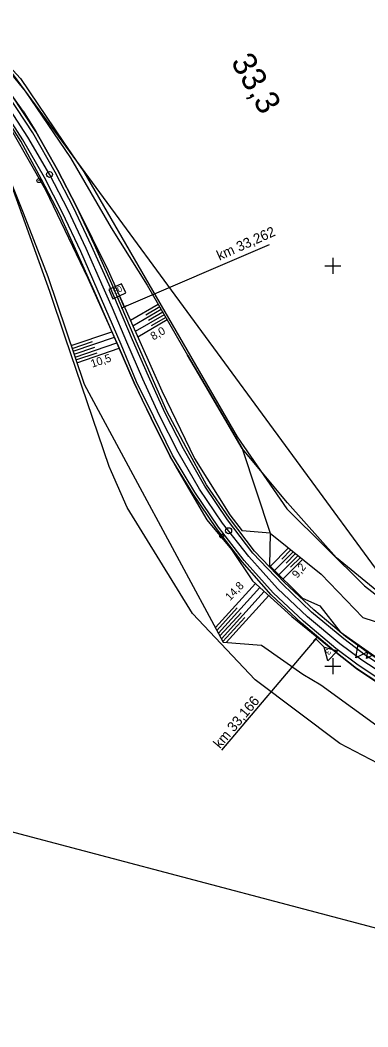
# Model space of a CAD drawing. Extents: x -805011 to -803920, y -1150790 to -1150234.
# Drawn here: x -804178.2 to -804091.2, y -1150790.1 to -1150538.7 of the extents above; entities that cross this region are included whole.
import ezdxf

# ---------------------------------------------------------------- set-up
doc = ezdxf.new("R2010")
doc.units = 0
for name, color, linetype in [('0381KM032-037P - Vrstva 1', 7, 'Continuous'), ('0381KM032-037P - Vrstva 17', 7, 'Continuous'), ('0381KM032-037P - Vrstva 4', 7, 'Continuous'), ('0381KM032-037P - Vrstva 48', 7, 'Continuous'), ('0381KM032-037P - Vrstva 49', 7, 'Continuous'), ('0381KM032-037P - Vrstva 5', 7, 'Continuous'), ('0381KM032-037P - Vrstva 50', 7, 'Continuous'), ('0381KM032-037P - Vrstva 7', 7, 'Continuous'), ('formát', 7, 'Continuous'), ('hran DP - hran DP', 7, 'Continuous'), ('krizky_1000 - Vrstva 1', 7, 'Continuous'), ('vyt_sit - polygon', 7, 'Continuous')]:
    doc.layers.add(name, color=color, linetype=linetype)

msp = doc.modelspace()

# ---------------------------------------------------------------- linework, layer by layer
at = {"layer": '0381KM032-037P - Vrstva 1'}
for points in [[(-804170.82, -1150577.3), (-804176.26, -1150567.85), (-804182.37, -1150558.45), (-804188.8, -1150549.63), (-804195.8, -1150541.09), (-804203.2, -1150532.98), (-804210.73, -1150525.57), (-804219.76, -1150517.68), (-804222.98, -1150515.09)], [(-804121.06, -1150672.62), (-804127.59, -1150664.31), (-804133.36, -1150655.8), (-804138.71, -1150646.59), (-804143.42, -1150637.27), (-804147.52, -1150628.35), (-804151.54, -1150619.12), (-804155.16, -1150610.64), (-804157.42, -1150605.4), (-804161.72, -1150595.74), (-804166.25, -1150586.16), (-804170.82, -1150577.3)], [(-803978.41, -1150722.71), (-803983.51, -1150723.68), (-803993.92, -1150724.91), (-804004.46, -1150725.42), (-804014.95, -1150725.21), (-804025.47, -1150724.25), (-804035.41, -1150722.67), (-804044.08, -1150720.74), (-804054.77, -1150717.61), (-804064.47, -1150714.03), (-804074.16, -1150709.61), (-804083.95, -1150704.25), (-804092.73, -1150698.52), (-804098.22, -1150694.46), (-804106.33, -1150687.73), (-804113.82, -1150680.6), (-804121.06, -1150672.62)]]:
    msp.add_lwpolyline(points, dxfattribs=at)
at = {"layer": '0381KM032-037P - Vrstva 17'}
for points in [[(-804099.12, -1150672.95), (-804111.38, -1150659.24), (-804122.71, -1150645.64), (-804131.91, -1150629.82), (-804136.37, -1150622.31)], [(-804059.54, -1150698.86), (-804062.04, -1150700.07), (-804077.59, -1150690.55), (-804099.12, -1150672.95)]]:
    msp.add_lwpolyline(points, dxfattribs=at)
at = {"layer": '0381KM032-037P - Vrstva 4'}
for points in [[(-804155.31, -1150604.52), (-804159.65, -1150594.76), (-804164.13, -1150585.17), (-804168.86, -1150576.08), (-804174.28, -1150566.45), (-804180.44, -1150557.11), (-804187.11, -1150547.91)], [(-804159.67, -1150606.25), (-804163.99, -1150596.78), (-804168.29, -1150587.2), (-804172.88, -1150578.5), (-804178.08, -1150568.91), (-804181.43, -1150563.5), (-804184.18, -1150559.55), (-804190.46, -1150550.87)], [(-804158.94, -1150605.89), (-804163.07, -1150596.41), (-804167.66, -1150586.77), (-804172.11, -1150577.99), (-804177.55, -1150568.56), (-804183.56, -1150559.32), (-804190.06, -1150550.44)], [(-804155.96, -1150604.81), (-804160.35, -1150595.07), (-804164.87, -1150585.5), (-804169.43, -1150576.62), (-804175.01, -1150566.82), (-804181.12, -1150557.55), (-804187.68, -1150548.56)], [(-804135, -1150656.89), (-804140.73, -1150647.62), (-804145.48, -1150638.07), (-804149.71, -1150629.27), (-804153.71, -1150619.99), (-804159.67, -1150606.25)], [(-804134.56, -1150656.61), (-804140.15, -1150647.32), (-804144.81, -1150637.78), (-804149.09, -1150628.99), (-804152.99, -1150619.67), (-804158.94, -1150605.89)], [(-804132.06, -1150655.06), (-804137.36, -1150645.71), (-804142.06, -1150636.68), (-804146.12, -1150627.62), (-804150.08, -1150618.55), (-804155.96, -1150604.81)], [(-804131.6, -1150654.76), (-804136.67, -1150645.43), (-804141.53, -1150636.36), (-804145.41, -1150627.43), (-804149.44, -1150618.25), (-804155.31, -1150604.52)], [(-804073.38, -1150708.29), (-804083.27, -1150702.88), (-804091.89, -1150697.28), (-804097.27, -1150693.2), (-804105.34, -1150686.53), (-804112.64, -1150679.57), (-804120.03, -1150671.79), (-804126.35, -1150663.48), (-804132.06, -1150655.06)], [(-804073.1, -1150707.59), (-804077.68, -1150705.14), (-804082.78, -1150702.25), (-804091.44, -1150696.56), (-804096.83, -1150692.65), (-804104.73, -1150685.98), (-804112.1, -1150679.17), (-804119.6, -1150671.34), (-804125.86, -1150663.1), (-804131.6, -1150654.76)], [(-804075.18, -1150711.95), (-804085.34, -1150706.36), (-804094.07, -1150700.58), (-804099.68, -1150696.17), (-804107.82, -1150689.29), (-804115.4, -1150682.25), (-804122.72, -1150674.01), (-804129.15, -1150665.64), (-804135, -1150656.89)], [(-804074.79, -1150711.15), (-804084.84, -1150705.62), (-804093.69, -1150699.81), (-804099.23, -1150695.65), (-804107.33, -1150688.8), (-804114.94, -1150681.73), (-804122.23, -1150673.64), (-804128.61, -1150665.3), (-804134.56, -1150656.61)]]:
    msp.add_lwpolyline(points, dxfattribs=at)
at = {"layer": '0381KM032-037P - Vrstva 48'}
for p, q in [((-804143.67, -1150609.66), (-804150.65, -1150613.69)), ((-804142.92, -1150610.96), (-804150.03, -1150615.07)), ((-804143.3, -1150610.31), (-804146.82, -1150612.35)), ((-804142.17, -1150612.26), (-804149.42, -1150616.44)), ((-804141.42, -1150613.56), (-804148.81, -1150617.82)), ((-804142.55, -1150611.61), (-804146.14, -1150613.68)), ((-804141.8, -1150612.91), (-804145.46, -1150615.02)), ((-804165.46, -1150619.97), (-804155.27, -1150616.52)), ((-804164.98, -1150621.39), (-804154.65, -1150617.89)), ((-804165.22, -1150620.68), (-804160.09, -1150618.94)), ((-804164.74, -1150622.1), (-804159.54, -1150620.34)), ((-804164.5, -1150622.81), (-804154.04, -1150619.27)), ((-804164.02, -1150624.23), (-804153.43, -1150620.64)), ((-804164.26, -1150623.52), (-804158.99, -1150621.74)), ((-804111.08, -1150670.5), (-804115.64, -1150675.08)), ((-804109.9, -1150671.45), (-804114.57, -1150676.14)), ((-804110.49, -1150670.98), (-804112.8, -1150673.29)), ((-804108.72, -1150672.39), (-804113.51, -1150677.2)), ((-804107.54, -1150673.33), (-804112.45, -1150678.26)), ((-804109.31, -1150671.92), (-804111.68, -1150674.29)), ((-804108.13, -1150672.86), (-804110.56, -1150675.3)), ((-804129.38, -1150690.39), (-804119.38, -1150679.38)), ((-804128.63, -1150691.79), (-804118.27, -1150680.39)), ((-804127.87, -1150693.19), (-804117.16, -1150681.39)), ((-804126.68, -1150694.11), (-804116.05, -1150682.4)), ((-804129.01, -1150691.09), (-804123.91, -1150685.49)), ((-804128.25, -1150692.49), (-804122.98, -1150686.69)), ((-804127.5, -1150693.89), (-804122.05, -1150687.9))]:
    msp.add_line(p, q, dxfattribs=at)
at = {"layer": '0381KM032-037P - Vrstva 49'}
for q in [(-804122.66, -1150666.25), (-804115.86, -1150674.86)]:
    msp.add_line((-804115.71, -1150666.79), q, dxfattribs=at)
for points in [[(-804216.26, -1150515.03), (-804196.49, -1150533.54), (-804188.66, -1150542.31), (-804183.72, -1150548.22), (-804177, -1150556.4), (-804165.66, -1150573.06), (-804155.49, -1150590.5), (-804146.45, -1150604.86), (-804136.37, -1150622.31), (-804131.91, -1150629.82), (-804122.71, -1150645.64), (-804115.71, -1150666.79), (-804102.89, -1150677.06), (-804092.51, -1150687.92), (-804076.71, -1150692.97), (-804062.72, -1150701.97), (-804052.08, -1150706.52)], [(-804177.46, -1150561.39), (-804180.44, -1150557.11), (-804187.34, -1150547.5), (-804194.06, -1150539.52)], [(-804190.46, -1150550.87), (-804184.18, -1150559.55), (-804171.89, -1150581.01)], [(-804191.88, -1150555.68), (-804187.09, -1150562.15), (-804183.47, -1150572.06), (-804177.47, -1150586.83), (-804171.32, -1150602.68), (-804162.19, -1150629.63), (-804127.41, -1150694.05), (-804117.85, -1150694.76), (-804107.49, -1150702.04), (-804103.03, -1150704.73), (-804070.42, -1150728.33), (-804053.81, -1150732.63), (-804001.62, -1150732.39)], [(-804177.46, -1150561.39), (-804174.28, -1150566.45), (-804168.86, -1150576.08), (-804164.13, -1150585.17), (-804156.2, -1150601.21), (-804142.82, -1150631.28), (-804134.64, -1150648.13), (-804125.75, -1150662.22), (-804122.66, -1150666.25)], [(-804171.89, -1150581.01), (-804161.29, -1150603.14), (-804153.71, -1150619.99), (-804149.71, -1150629.27), (-804147.81, -1150633.31), (-804145.48, -1150638.07), (-804140.73, -1150647.62), (-804139.02, -1150650.67), (-804131.55, -1150663.46), (-804125.32, -1150670.91), (-804120.07, -1150678.75), (-804110.3, -1150687.62), (-804101.36, -1150694.88), (-804099.68, -1150696.17), (-804094.07, -1150700.58), (-804090.5, -1150703.01), (-804085.34, -1150706.36), (-804081.43, -1150711.18)], [(-804115.86, -1150674.86), (-804107.6, -1150683.08), (-804103.3, -1150684.96), (-804098.16, -1150691.46), (-804087.29, -1150699.16)]]:
    msp.add_lwpolyline(points, dxfattribs=at)
at = {"layer": '0381KM032-037P - Vrstva 5'}
for p, q in [((-804152.17, -1150610.26), (-804115.82, -1150594.67)), ((-804152.87, -1150610.57), (-804151.5, -1150609.96)), ((-804104.29, -1150693.19), (-804127.82, -1150721.03)), ((-804103.76, -1150692.66), (-804104.82, -1150693.72))]:
    msp.add_line(p, q, dxfattribs=at)
for points in [[(-804152.18, -1150610.26), (-804153.41, -1150607.52), (-804151.81, -1150606.81), (-804152.83, -1150604.53), (-804156.03, -1150605.96), (-804155.01, -1150608.24), (-804153.41, -1150607.52)], [(-804104.29, -1150693.19), (-804102.17, -1150695.31), (-804098.81, -1150696.19), (-804101.28, -1150698.67), (-804102.17, -1150695.31)]]:
    msp.add_lwpolyline(points, dxfattribs=at)
at = {"layer": '0381KM032-037P - Vrstva 50'}
msp.add_lwpolyline([(-804090.07, -1150697.33), (-804091.56, -1150698.09), (-804091.28, -1150696.44), (-804094.26, -1150697.96), (-804093.69, -1150694.66)], dxfattribs=at)
at = {"layer": '0381KM032-037P - Vrstva 7'}
for p, q in [((-804173.51, -1150578.79), (-804173.56, -1150578.7)), ((-804127.76, -1150667.59), (-804127.82, -1150667.51))]:
    msp.add_line(p, q, dxfattribs=at)
for centre, radius in [((-804173.53, -1150578.75), 0.5), ((-804170.87, -1150577.21), 0.75), ((-804126.09, -1150666.21), 0.75), ((-804127.79, -1150667.55), 0.5)]:
    msp.add_circle(centre, radius, dxfattribs=at)
at = {"layer": 'formát'}
msp.add_line((-803996.25, -1150790.14), (-804199.27, -1150736.42), dxfattribs=at)
at = {"layer": 'hran DP - hran DP'}
for p, q in [((-804196.65, -1150533.37), (-804178.11, -1150553.27)), ((-804178.11, -1150553.27), (-804167.37, -1150569.11)), ((-804167.37, -1150569.11), (-804162.29, -1150576.56)), ((-804170.78, -1150606.46), (-804182.55, -1150573.8)), ((-804162.29, -1150576.56), (-804123.96, -1150642.72)), ((-804166.92, -1150617.84), (-804170.78, -1150606.46)), ((-804155.97, -1150650.2), (-804166.92, -1150617.84)), ((-804123.96, -1150642.72), (-804111.51, -1150660.72)), ((-804155.38, -1150651.53), (-804155.97, -1150650.2)), ((-804151.42, -1150660.42), (-804155.38, -1150651.53)), ((-804135.09, -1150686.84), (-804151.42, -1150660.42)), ((-804111.51, -1150660.72), (-804092.1, -1150680)), ((-804092.1, -1150680), (-804079.43, -1150689.81)), ((-804119.46, -1150703.45), (-804135.09, -1150686.84)), ((-804098.25, -1150719.35), (-804119.46, -1150703.45)), ((-804086.77, -1150725.31), (-804098.25, -1150719.35))]:
    msp.add_line(p, q, dxfattribs=at)
at = {"layer": 'krizky_1000 - Vrstva 1'}
for points in [[(-804100, -1150598), (-804100, -1150602)], [(-804102, -1150600), (-804098, -1150600)], [(-804100, -1150698), (-804100, -1150702)], [(-804102, -1150700), (-804098, -1150700)]]:
    msp.add_lwpolyline(points, dxfattribs=at)
at = {"layer": 'vyt_sit - polygon'}
msp.add_line((-804184.81, -1150545.81), (-804054.72, -1150722.82), dxfattribs=at)

# ---------------------------------------------------------------- texts
at = {"layer": '0381KM032-037P - Vrstva 48'}
for s, rotation, p in [('8,0', 29.9889, (-804144.91, -1150618.69)), ('10,5', 18.3536, (-804160.19, -1150625.49)), ('9,2', 51.2857, (-804108.89, -1150678.22)), ('14,8', 45.8956, (-804125.73, -1150683.84))]:
    msp.add_text(s, height=2, rotation=rotation, dxfattribs=at).set_placement(p)
at = {"layer": '0381KM032-037P - Vrstva 5'}
for s, height, rotation, p in [('km 33,262', 2.5, 24.1108, (-804128.38, -1150598.75)), ('50', 1.5, 24.1108, (-804154.55, -1150607.21)), ('3', 1.5, 225.0712, (-804101.33, -1150695.53)), ('km 33,166', 2.5, 50.0712, (-804128.22, -1150720.78))]:
    msp.add_text(s, height=height, rotation=rotation, dxfattribs=at).set_placement(p)
at = {"layer": '0381KM032-037P - Vrstva 7'}
msp.add_text('33,3', height=6, rotation=299.9223, dxfattribs=at).set_placement((-804125.64, -1150549.08))

doc.saveas('drawing.dxf')
